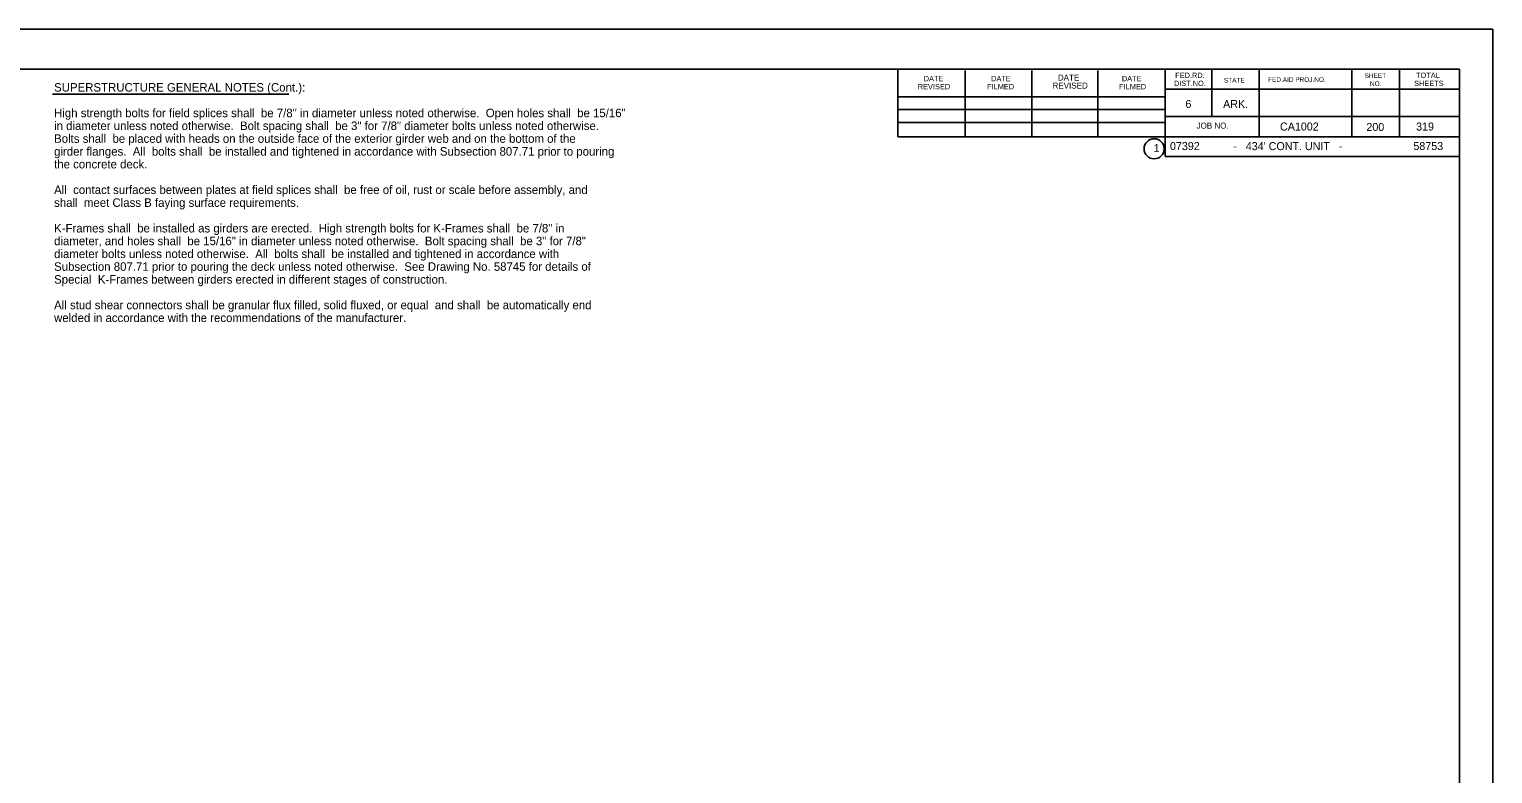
# Model space of a CAD drawing. Extents: x -1771525.8 to -1771491.7, y -422628.7 to -422606.9.
# Drawn here: x -1771513.1 to -1771491.67, y -422617.81 to -422606.91 of the extents above; entities that cross this region are included whole.
import ezdxf

# ---------------------------------------------------------------- set-up
doc = ezdxf.new("R2010")
doc.units = 0
for name, color, linetype in [('border', 7, 'Continuous'), ('Border 2660-Hwy18 - Level 62', 7, 'Continuous'), ('Border 2660-Hwy18 - Text', 7, 'Continuous'), ('Bridge No BLFR', 7, 'Continuous'), ('Level 40', 7, 'Continuous'), ('Text', 7, 'Continuous'), ('Title Text', 7, 'Continuous')]:
    doc.layers.add(name, color=color, linetype=linetype)

msp = doc.modelspace()

# ---------------------------------------------------------------- linework, layer by layer
at = {"layer": 'border'}
for p, q in [((-1771524.168, -422607.492), (-1771492.157, -422607.492)), ((-1771500.383, -422608.48), (-1771500.383, -422607.492)), ((-1771499.398, -422608.48), (-1771499.398, -422607.512)), ((-1771498.421, -422608.48), (-1771498.421, -422607.512)), ((-1771497.454, -422608.48), (-1771497.454, -422607.512)), ((-1771496.468, -422607.492), (-1771496.468, -422608.772)), ((-1771495.784, -422607.492), (-1771495.784, -422608.186)), ((-1771495.089, -422607.492), (-1771495.089, -422608.48)), ((-1771493.732, -422607.492), (-1771493.732, -422608.48)), ((-1771493.037, -422607.492), (-1771493.037, -422608.48)), ((-1771492.157, -422628.038), (-1771492.157, -422607.492)), ((-1771492.157, -422607.786), (-1771496.468, -422607.786)), ((-1771492.157, -422607.784), (-1771492.157, -422607.784)), ((-1771500.383, -422607.894), (-1771496.468, -422607.894)), ((-1771500.383, -422608.08), (-1771496.468, -422608.08)), ((-1771500.383, -422608.48), (-1771500.383, -422608.274)), ((-1771500.383, -422608.274), (-1771496.468, -422608.274)), ((-1771492.157, -422608.186), (-1771496.468, -422608.186)), ((-1771496.171, -422608.186), (-1771492.157, -422608.186)), ((-1771492.157, -422608.48), (-1771500.383, -422608.48)), ((-1771496.468, -422608.772), (-1771492.157, -422608.772))]:
    msp.add_line(p, q, dxfattribs=at)
msp.add_circle((-1771496.629, -422608.658), 0.147, dxfattribs=at)
at = {"layer": 'Border 2660-Hwy18 - Level 62'}
msp.add_lwpolyline([(-1771525.789, -422606.907), (-1771491.67, -422606.907), (-1771491.67, -422628.716), (-1771525.789, -422628.716)], close=True, dxfattribs=at)
at = {"layer": 'Level 40'}
msp.add_line((-1771512.76, -422607.857), (-1771509.301, -422607.857), dxfattribs=at)

# ---------------------------------------------------------------- texts
at = {"layer": 'Border 2660-Hwy18 - Text'}
for s, height, p in [('DATE', 0.0782, (-1771500.003, -422607.668)), ('DATE', 0.0782, (-1771499.016, -422607.668)), ('DATE', 0.0879, (-1771498.038, -422607.658)), ('DATE', 0.0782, (-1771497.101, -422607.668)), ('DIST.NO.', 0.0782, (-1771496.339, -422607.738)), ('FED.RD.', 0.0782, (-1771496.32, -422607.62)), ('STATE', 0.0684, (-1771495.607, -422607.688)), ('FED.AID PROJ.NO.', 0.06839, (-1771494.96, -422607.678)), ('SHEET', 0.0684, (-1771493.546, -422607.62)), ('NO.', 0.0684, (-1771493.468, -422607.738)), ('SHEETS', 0.0782, (-1771492.822, -422607.738)), ('TOTAL', 0.0782, (-1771492.793, -422607.62)), ('REVISED', 0.0782, (-1771500.09, -422607.786)), ('FILMED', 0.0782, (-1771499.075, -422607.786)), ('REVISED', 0.0879, (-1771498.116, -422607.776)), ('FILMED', 0.0782, (-1771497.141, -422607.786)), ('6', 0.117, (-1771496.17, -422608.06)), ('ARK.', 0.1172, (-1771495.618, -422608.06)), ('JOB NO.', 0.0879, (-1771496.007, -422608.362)), ('CA1002', 0.1172, (-1771494.785, -422608.39)), ('319', 0.1172, (-1771492.792, -422608.39)), ('1', 0.117, (-1771496.636, -422608.706))]:
    msp.add_text(s, height=height, dxfattribs=at).set_placement(p)
at = {"layer": 'Bridge No BLFR'}
msp.add_text('07392', height=0.1172, dxfattribs=at).set_placement((-1771496.397, -422608.676))
at = {"layer": 'Level 40'}
for s, p in [('SUPERSTRUCTURE GENERAL NOTES (Cont.):', (-1771512.738, -422607.82)), ('High strength bolts for field splices shall  be 7/8" in diameter unless noted otherwise.  Open holes shall  be 15/16" ', (-1771512.738, -422608.195)), ('in diameter unless noted otherwise.  Bolt spacing shall  be 3" for 7/8" diameter bolts unless noted otherwise.  ', (-1771512.738, -422608.383)), ('Bolts shall  be placed with heads on the outside face of the exterior girder web and on the bottom of the ', (-1771512.738, -422608.57)), ('girder flanges.  All  bolts shall  be installed and tightened in accordance with Subsection 807.71 prior to pouring ', (-1771512.738, -422608.758)), ('the concrete deck.', (-1771512.738, -422608.945)), ('All  contact surfaces between plates at field splices shall  be free of oil, rust or scale before assembly, and ', (-1771512.738, -422609.32)), ('shall  meet Class B faying surface requirements.', (-1771512.738, -422609.508)), ('K-Frames shall  be installed as girders are erected.  High strength bolts for K-Frames shall  be 7/8" in ', (-1771512.738, -422609.883)), ('diameter, and holes shall  be 15/16" in diameter unless noted otherwise.  Bolt spacing shall  be 3" for 7/8" ', (-1771512.738, -422610.07)), ('diameter bolts unless noted otherwise.  All  bolts shall  be installed and tightened in accordance with ', (-1771512.738, -422610.258)), ('Subsection 807.71 prior to pouring the deck unless noted otherwise.  See Drawing No. 58745 for details of ', (-1771512.738, -422610.445)), ('Special  K-Frames between girders erected in different stages of construction.', (-1771512.738, -422610.633)), ('All stud shear connectors shall be granular flux filled, solid fluxed, or equal  and shall  be automatically end ', (-1771512.738, -422611.008)), ('welded in accordance with the recommendations of the manufacturer.', (-1771512.738, -422611.195))]:
    msp.add_text(s, height=0.125, dxfattribs=at).set_placement(p)
at = {"layer": 'Text'}
msp.add_text('200', height=0.1172, dxfattribs=at).set_placement((-1771493.52, -422608.397))
at = {"layer": 'Title Text'}
for s, height, p in [("-   434' CONT. UNIT   -", 0.11722, (-1771495.469, -422608.677)), ('58753', 0.1172, (-1771492.832, -422608.676))]:
    msp.add_text(s, height=height, dxfattribs=at).set_placement(p)

doc.saveas('drawing.dxf')
